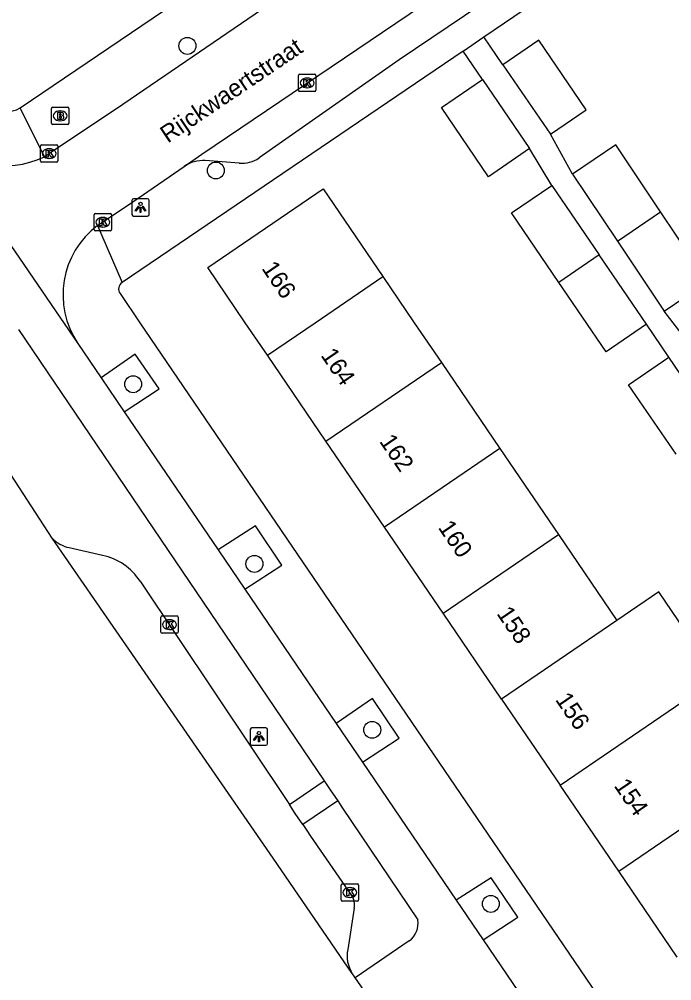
# Model space of a CAD drawing. Extents: x 160037 to 160839, y 385326 to 386441.
# Drawn here: x 160118.7 to 160156.4, y 385962.1 to 386017.5 of the extents above; entities that cross this region are included whole.
import ezdxf

# ---------------------------------------------------------------- set-up
doc = ezdxf.new("R2010")
doc.units = 0
for name, color, linetype in [('IMGEO_Boom', 7, 'Continuous'), ('IMGEO_Brandkraan', 7, 'Continuous'), ('IMGEO_Fietspad_gesloten', 7, 'Continuous'), ('IMGEO_Kolk', 7, 'Continuous'), ('IMGEO_Lichtpunt', 7, 'Continuous'), ('IMGEO_Openbare_ruimte_label', 7, 'Continuous'), ('IMGEO_Pand', 7, 'Continuous'), ('IMGEO_Pand_nummerreeks', 7, 'Continuous'), ('IMGEO_Parkeervlak_open', 7, 'Continuous'), ('IMGEO_Rijbaan_lokaal_gesloten', 7, 'Continuous'), ('IMGEO_Rijbaan_lokaal_open', 7, 'Continuous'), ('IMGEO_Voetpad_open', 7, 'Continuous')]:
    doc.layers.add(name, color=color, linetype=linetype)

msp = doc.modelspace()

# ---------------------------------------------------------------- linework, layer by layer
at = {"layer": 'IMGEO_Boom'}
for centre in [(160128.397, 386015.969), (160130.04, 386008.784), (160125.268, 385996.455), (160132.266, 385986.096), (160139.065, 385976.526), (160145.912, 385966.485)]:
    msp.add_circle(centre, 0.489, dxfattribs=at)
at = {"layer": 'IMGEO_Brandkraan'}
for p, q in [((160120.627, 386012.435), (160121.479, 386012.435)), ((160120.552, 386011.509), (160120.552, 386012.361)), ((160121.04, 386012.215), (160121.065, 386012.215)), ((160121.553, 386012.361), (160121.553, 386011.509)), ((160121.479, 386011.435), (160120.627, 386011.435)), ((160121.063, 386011.655), (160121.038, 386011.655))]:
    msp.add_line(p, q, dxfattribs=at)
for points in [[(160120.627, 386012.435), (160121.479, 386012.435)], [(160120.552, 386011.509), (160120.552, 386012.361)], [(160120.9, 386012.135), (160120.9, 386011.735), (160121.113, 386011.735)], [(160121.131, 386012.135), (160120.9, 386012.135)], [(160121.079, 386012.054), (160121.025, 386012.054), (160121.025, 386011.978)], [(160121.025, 386011.978), (160121.078, 386011.978)], [(160121.087, 386011.902), (160121.025, 386011.902), (160121.025, 386011.821)], [(160121.553, 386012.361), (160121.553, 386011.509)], [(160121.479, 386011.435), (160120.627, 386011.435)], [(160121.025, 386011.821), (160121.087, 386011.821)]]:
    msp.add_lwpolyline(points, dxfattribs=at)
for centre, radius, start, end in [((160120.629, 386012.359), 0.0765, 91.552, 178.448), ((160120.629, 386012.359), 0.0765, 91.552, 178.448), ((160121.477, 386012.359), 0.0765, 1.552, 88.448), ((160121.477, 386012.359), 0.0765, 1.552, 88.448), ((160121.08, 386012.016), 0.0379, 267.8285, 90.9355), ((160121.088, 386011.861), 0.0404, 269.8759, 90.5077), ((160121.135, 386011.99), 0.145, 59.4692, 91.5367), ((160121.16, 386012.037), 0.0922, 285.5137, 58.1501), ((160121.165, 386011.845), 0.105, 301.3115, 78.989), ((160120.629, 386011.511), 0.0765, 181.552, 268.448), ((160120.629, 386011.511), 0.0765, 181.552, 268.448), ((160121.119, 386011.986), 0.251, 268.6676, 293.5347), ((160121.477, 386011.511), 0.0765, 271.552, 358.448), ((160121.477, 386011.511), 0.0765, 271.552, 358.448)]:
    msp.add_arc(centre, radius, start, end, dxfattribs=at)
for centre, major_axis, ratio, start_param, end_param in [((160121.039, 386011.935), (-0.387, 0.002), 0.722429, 4.712389, 7.853982), ((160121.064, 386011.935), (-0.39, 0.002), 0.717154, 1.570796, 4.712389)]:
    msp.add_ellipse(centre, major_axis=major_axis, ratio=ratio, start_param=start_param, end_param=end_param, dxfattribs=at)
at = {"layer": 'IMGEO_Fietspad_gesloten'}
for points in [[(160118.645, 385999.609), (160136.295, 385973.586)], [(160122.081, 385998.808), (160123.429, 385996.826)], [(160123.429, 385996.826), (160124.758, 385994.871)], [(160124.758, 385994.871), (160130.172, 385986.909)], [(160130.172, 385986.909), (160131.713, 385984.643)], [(160131.713, 385984.643), (160136.979, 385976.896)], [(160136.979, 385976.896), (160138.5, 385974.658)], [(160138.5, 385974.658), (160143.914, 385966.694)], [(160136.295, 385973.586), (160136.648, 385973.065), (160137.081, 385972.428)], [(160137.081, 385972.428), (160137.322, 385972.072), (160141.694, 385965.572)], [(160143.914, 385966.694), (160145.465, 385964.411)], [(160141.197, 385964.348), (160138.083, 385962.227)], [(160145.465, 385964.411), (160150.233, 385957.4)]]:
    msp.add_lwpolyline(points, dxfattribs=at)
msp.add_arc((160140.463, 385965.359), 1.249, 305.9754, 9.8258, dxfattribs=at)
at = {"layer": 'IMGEO_Kolk'}
for p, q in [((160134.806, 386013.407), (160134.806, 386014.259)), ((160134.881, 386014.333), (160135.733, 386014.333)), ((160135.294, 386014.113), (160135.319, 386014.113)), ((160135.807, 386014.259), (160135.807, 386013.407)), ((160135.317, 386013.553), (160135.292, 386013.553)), ((160135.733, 386013.333), (160134.881, 386013.333)), ((160119.998, 386010.259), (160120.85, 386010.259)), ((160119.923, 386009.333), (160119.923, 386010.185)), ((160120.411, 386010.039), (160120.436, 386010.039)), ((160120.924, 386010.185), (160120.924, 386009.333)), ((160120.85, 386009.259), (160119.998, 386009.259)), ((160120.434, 386009.479), (160120.409, 386009.479)), ((160123.014, 386005.372), (160123.014, 386006.224)), ((160123.089, 386006.298), (160123.941, 386006.298)), ((160123.502, 386006.078), (160123.527, 386006.078)), ((160124.015, 386006.224), (160124.015, 386005.372)), ((160123.941, 386005.298), (160123.089, 386005.298)), ((160123.525, 386005.518), (160123.5, 386005.518)), ((160126.944, 385983.091), (160127.796, 385983.091)), ((160126.869, 385982.165), (160126.869, 385983.017)), ((160127.357, 385982.871), (160127.382, 385982.871)), ((160127.87, 385983.017), (160127.87, 385982.165)), ((160127.796, 385982.091), (160126.944, 385982.091)), ((160127.38, 385982.311), (160127.355, 385982.311)), ((160137.277, 385966.718), (160137.277, 385967.57)), ((160137.352, 385967.644), (160138.204, 385967.644)), ((160138.278, 385967.57), (160138.278, 385966.718)), ((160137.765, 385967.424), (160137.79, 385967.424)), ((160138.204, 385966.644), (160137.352, 385966.644)), ((160137.788, 385966.864), (160137.763, 385966.864))]:
    msp.add_line(p, q, dxfattribs=at)
for points in [[(160134.806, 386013.407), (160134.806, 386014.259)], [(160134.881, 386014.333), (160135.733, 386014.333)], [(160135.807, 386014.259), (160135.807, 386013.407)], [(160135.127, 386014.033), (160135.25, 386014.033), (160135.25, 386013.882), (160135.38, 386014.033), (160135.544, 386014.033), (160135.398, 386013.882), (160135.551, 386013.633), (160135.399, 386013.633), (160135.314, 386013.797), (160135.25, 386013.73), (160135.25, 386013.633), (160135.127, 386013.633), (160135.127, 386014.033)], [(160135.733, 386013.333), (160134.881, 386013.333)], [(160119.998, 386010.259), (160120.85, 386010.259)], [(160119.923, 386009.333), (160119.923, 386010.185)], [(160120.244, 386009.959), (160120.367, 386009.959), (160120.367, 386009.808), (160120.497, 386009.959), (160120.661, 386009.959), (160120.515, 386009.808), (160120.668, 386009.559), (160120.516, 386009.559), (160120.431, 386009.723), (160120.367, 386009.656), (160120.367, 386009.559), (160120.244, 386009.559), (160120.244, 386009.959)], [(160120.924, 386010.185), (160120.924, 386009.333)], [(160120.85, 386009.259), (160119.998, 386009.259)], [(160123.014, 386005.372), (160123.014, 386006.224)], [(160123.089, 386006.298), (160123.941, 386006.298)], [(160123.335, 386005.998), (160123.458, 386005.998), (160123.458, 386005.847), (160123.588, 386005.998), (160123.752, 386005.998), (160123.606, 386005.847), (160123.759, 386005.598), (160123.607, 386005.598), (160123.522, 386005.762), (160123.458, 386005.695), (160123.458, 386005.598), (160123.335, 386005.598), (160123.335, 386005.998)], [(160124.015, 386006.224), (160124.015, 386005.372)], [(160123.941, 386005.298), (160123.089, 386005.298)], [(160126.944, 385983.091), (160127.796, 385983.091)], [(160126.869, 385982.165), (160126.869, 385983.017)], [(160127.19, 385982.791), (160127.313, 385982.791), (160127.313, 385982.64), (160127.443, 385982.791), (160127.607, 385982.791), (160127.461, 385982.64), (160127.614, 385982.391), (160127.462, 385982.391), (160127.377, 385982.555), (160127.313, 385982.488), (160127.313, 385982.391), (160127.19, 385982.391), (160127.19, 385982.791)], [(160127.87, 385983.017), (160127.87, 385982.165)], [(160127.796, 385982.091), (160126.944, 385982.091)], [(160137.277, 385966.718), (160137.277, 385967.57)], [(160137.352, 385967.644), (160138.204, 385967.644)], [(160138.278, 385967.57), (160138.278, 385966.718)], [(160137.598, 385967.344), (160137.721, 385967.344), (160137.721, 385967.193), (160137.851, 385967.344), (160138.015, 385967.344), (160137.869, 385967.193), (160138.022, 385966.944), (160137.87, 385966.944), (160137.785, 385967.108), (160137.721, 385967.041), (160137.721, 385966.944), (160137.598, 385966.944), (160137.598, 385967.344)], [(160138.204, 385966.644), (160137.352, 385966.644)]]:
    msp.add_lwpolyline(points, dxfattribs=at)
for centre, start, end in [((160134.883, 386014.257), 91.552, 178.448), ((160134.883, 386014.257), 91.552, 178.448), ((160135.731, 386014.257), 1.552, 88.448), ((160135.731, 386014.257), 1.552, 88.448), ((160134.883, 386013.409), 181.552, 268.448), ((160134.883, 386013.409), 181.552, 268.448), ((160135.731, 386013.409), 271.552, 358.448), ((160135.731, 386013.409), 271.552, 358.448), ((160120, 386010.183), 91.552, 178.448), ((160120, 386010.183), 91.552, 178.448), ((160120.848, 386010.183), 1.552, 88.448), ((160120.848, 386010.183), 1.552, 88.448), ((160120, 386009.335), 181.552, 268.448), ((160120, 386009.335), 181.552, 268.448), ((160120.848, 386009.335), 271.552, 358.448), ((160120.848, 386009.335), 271.552, 358.448), ((160123.091, 386006.222), 91.552, 178.448), ((160123.091, 386006.222), 91.552, 178.448), ((160123.939, 386006.222), 1.552, 88.448), ((160123.939, 386006.222), 1.552, 88.448), ((160123.091, 386005.374), 181.552, 268.448), ((160123.091, 386005.374), 181.552, 268.448), ((160123.939, 386005.374), 271.552, 358.448), ((160123.939, 386005.374), 271.552, 358.448), ((160126.946, 385983.015), 91.552, 178.448), ((160126.946, 385983.015), 91.552, 178.448), ((160127.794, 385983.015), 1.552, 88.448), ((160127.794, 385983.015), 1.552, 88.448), ((160126.946, 385982.167), 181.552, 268.448), ((160126.946, 385982.167), 181.552, 268.448), ((160127.794, 385982.167), 271.552, 358.448), ((160127.794, 385982.167), 271.552, 358.448), ((160137.354, 385967.568), 91.552, 178.448), ((160137.354, 385967.568), 91.552, 178.448), ((160138.202, 385967.568), 1.552, 88.448), ((160138.202, 385967.568), 1.552, 88.448), ((160137.354, 385966.72), 181.552, 268.448), ((160137.354, 385966.72), 181.552, 268.448), ((160138.202, 385966.72), 271.552, 358.448), ((160138.202, 385966.72), 271.552, 358.448)]:
    msp.add_arc(centre, 0.0765, start, end, dxfattribs=at)
for centre, major_axis, ratio, start_param, end_param in [((160135.293, 386013.833), (-0.387, 0.002), 0.722429, 4.712389, 7.853982), ((160135.318, 386013.833), (-0.39, 0.002), 0.717154, 1.570796, 4.712389), ((160120.41, 386009.759), (-0.387, 0.002), 0.722429, 4.712389, 7.853982), ((160120.435, 386009.759), (-0.39, 0.002), 0.717154, 1.570796, 4.712389), ((160123.501, 386005.798), (-0.387, 0.002), 0.722429, 4.712389, 7.853982), ((160123.526, 386005.798), (-0.39, 0.002), 0.717154, 1.570796, 4.712389), ((160127.356, 385982.591), (-0.387, 0.002), 0.722429, 4.712389, 7.853982), ((160127.381, 385982.591), (-0.39, 0.002), 0.717154, 1.570796, 4.712389), ((160137.764, 385967.144), (-0.387, 0.002), 0.722429, 4.712389, 7.853982), ((160137.789, 385967.144), (-0.39, 0.002), 0.717154, 1.570796, 4.712389)]:
    msp.add_ellipse(centre, major_axis=major_axis, ratio=ratio, start_param=start_param, end_param=end_param, dxfattribs=at)
at = {"layer": 'IMGEO_Lichtpunt'}
for p, q in [((160125.197, 386007.059), (160125.197, 386006.252)), ((160125.197, 386007.059), (160125.197, 386006.252)), ((160126.099, 386007.154), (160125.291, 386007.154)), ((160126.099, 386007.154), (160125.291, 386007.154)), ((160126.193, 386006.252), (160126.193, 386007.059)), ((160126.193, 386006.252), (160126.193, 386007.059)), ((160125.291, 386006.158), (160126.099, 386006.158)), ((160125.291, 386006.158), (160126.099, 386006.158)), ((160132.028, 385976.54), (160132.028, 385975.733)), ((160132.028, 385976.54), (160132.028, 385975.733)), ((160132.93, 385976.635), (160132.122, 385976.635)), ((160132.93, 385976.635), (160132.122, 385976.635)), ((160133.024, 385975.733), (160133.024, 385976.54)), ((160133.024, 385975.733), (160133.024, 385976.54)), ((160132.122, 385975.639), (160132.93, 385975.639)), ((160132.122, 385975.639), (160132.93, 385975.639))]:
    msp.add_line(p, q, dxfattribs=at)
for points in [[(160125.571, 386006.723), (160125.61, 386006.695), (160125.422, 386006.433), (160125.384, 386006.46), (160125.571, 386006.723)], [(160125.673, 386006.675), (160125.72, 386006.675), (160125.72, 386006.353), (160125.673, 386006.353), (160125.673, 386006.675)], [(160125.783, 386006.695), (160125.821, 386006.722), (160126.008, 386006.46), (160125.969, 386006.432), (160125.783, 386006.695)], [(160132.402, 385976.204), (160132.441, 385976.176), (160132.253, 385975.914), (160132.215, 385975.941), (160132.402, 385976.204)], [(160132.504, 385976.156), (160132.551, 385976.156), (160132.551, 385975.834), (160132.504, 385975.834), (160132.504, 385976.156)], [(160132.614, 385976.176), (160132.652, 385976.203), (160132.839, 385975.941), (160132.8, 385975.913), (160132.614, 385976.176)]]:
    msp.add_lwpolyline(points, dxfattribs=at)
for centre in [(160125.696, 386006.857), (160132.527, 385976.338)]:
    msp.add_circle(centre, 0.0994, dxfattribs=at)
for centre, start, end in [((160125.291, 386007.059), 90, 180), ((160125.291, 386007.059), 90, 180), ((160126.099, 386007.059), 0, 90), ((160126.099, 386007.059), 0, 90), ((160125.291, 386006.252), 180, 270), ((160125.291, 386006.252), 180, 270), ((160126.099, 386006.252), 270, 0), ((160126.099, 386006.252), 270, 360), ((160132.122, 385976.54), 90, 180), ((160132.122, 385976.54), 90, 180), ((160132.93, 385976.54), 0, 90), ((160132.93, 385976.54), 0, 90), ((160132.122, 385975.733), 180, 270), ((160132.122, 385975.733), 180, 270), ((160132.93, 385975.733), 270, 0), ((160132.93, 385975.733), 270, 360)]:
    msp.add_arc(centre, 0.0946, start, end, dxfattribs=at)
at = {"layer": 'IMGEO_Pand'}
for points in [[(160149.354, 386010.869), (160151.42, 386012.283), (160148.674, 386016.298), (160146.608, 386014.884)], [(160146.608, 386014.884), (160149.354, 386010.869)], [(160148.149, 386010.046), (160145.782, 386008.427), (160143.058, 386012.409), (160145.425, 386014.028)], [(160145.425, 386014.028), (160148.149, 386010.046)], [(160155.713, 386006.402), (160153.125, 386010.255), (160150.622, 386008.574)], [(160150.622, 386008.574), (160153.214, 386004.713)], [(160133.017, 385998.126), (160131.74, 386000), (160129.572, 386003.181), (160136.231, 386007.72), (160139.676, 386002.666)], [(160149.841, 386002.33), (160147.108, 386006.339), (160149.435, 386007.925)], [(160149.435, 386007.925), (160152.168, 386003.916)], [(160153.214, 386004.713), (160155.713, 386006.402)], [(160155.924, 386000.678), (160158.424, 386002.367), (160155.713, 386006.402)], [(160153.214, 386004.713), (160155.924, 386000.678)], [(160152.168, 386003.916), (160149.841, 386002.33)], [(160154.895, 385999.915), (160152.168, 386003.916)], [(160133.017, 385998.126), (160135.766, 386000), (160139.676, 386002.666)], [(160139.676, 386002.666), (160141.493, 386000), (160143.056, 385997.707)], [(160154.895, 385999.915), (160152.569, 385998.33), (160149.841, 386002.33)], [(160136.397, 385993.168), (160133.017, 385998.126)], [(160156.6, 385992.416), (160153.867, 385996.425), (160156.193, 385998.01)], [(160158.926, 385994.001), (160156.193, 385998.01)], [(160136.397, 385993.168), (160143.056, 385997.707)], [(160143.056, 385997.707), (160146.435, 385992.75)], [(160139.776, 385988.21), (160136.397, 385993.168)], [(160146.435, 385992.75), (160139.776, 385988.21)], [(160146.435, 385992.75), (160149.814, 385987.792)], [(160143.155, 385983.253), (160139.776, 385988.21)], [(160143.155, 385983.253), (160149.814, 385987.792)], [(160149.814, 385987.792), (160153.194, 385982.834)], [(160156.574, 385977.876), (160158.983, 385979.518), (160155.603, 385984.476), (160153.194, 385982.834)], [(160146.535, 385978.295), (160143.155, 385983.253)], [(160153.194, 385982.834), (160146.535, 385978.295)], [(160146.535, 385978.295), (160149.914, 385973.337)], [(160149.914, 385973.337), (160156.574, 385977.876)], [(160153.293, 385968.379), (160149.914, 385973.337)], [(160153.293, 385968.379), (160159.953, 385972.919)], [(160156.673, 385963.421), (160153.293, 385968.379)]]:
    msp.add_lwpolyline(points, dxfattribs=at)
at = {"layer": 'IMGEO_Parkeervlak_open'}
for points in [[(160121.565, 385987.033), (160123.497, 385986.589)], [(160125.664, 385985.097), (160134.284, 385972.222)], [(160135.063, 385971.058), (160135.296, 385970.711), (160135.512, 385970.389), (160137.871, 385966.98)], [(160138.024, 385966.238), (160137.652, 385963.859)]]:
    msp.add_lwpolyline(points, dxfattribs=at)
for centre, radius, start, end in [((160121.984, 385988.922), 1.935, 224.1159, 257.4944), ((160122.793, 385983.247), 3.415, 32.7974, 78.107), ((160137.035, 385966.421), 1.006, 349.5336, 33.7686), ((160139.487, 385963.489), 1.872, 168.6094, 212.8794)]:
    msp.add_arc(centre, radius, start, end, dxfattribs=at)
at = {"layer": 'IMGEO_Rijbaan_lokaal_gesloten'}
for points in [[(160120.595, 385987.575), (160116.757, 385993.446)], [(160137.915, 385962.473), (160133.356, 385969.12), (160120.595, 385987.575)], [(160138.083, 385962.227), (160137.984, 385962.372), (160137.915, 385962.473)], [(160139.703, 385959.857), (160139.542, 385960.093), (160138.154, 385962.123), (160138.083, 385962.227)]]:
    msp.add_lwpolyline(points, dxfattribs=at)
at = {"layer": 'IMGEO_Rijbaan_lokaal_open'}
for points in [[(160159.266, 386036.142), (160139.533, 386022.738), (160124.669, 386012.596), (160120.145, 386009.569)], [(160128.204, 386009.022), (160129.232, 386009.733), (160151.628, 386024.852), (160157.666, 386028.94)], [(160113.781, 386010.901), (160122.081, 385998.808)], [(160123.219, 386005.61), (160125.251, 386006.979), (160128.204, 386009.022)]]:
    msp.add_lwpolyline(points, dxfattribs=at)
for centre, radius, start, end in [((160117.848, 386014.466), 5.408, 221.2297, 295.1273), ((160126.212, 386001.613), 4.993, 126.824, 214.1803)]:
    msp.add_arc(centre, radius, start, end, dxfattribs=at)
at = {"layer": 'IMGEO_Voetpad_open'}
for points in [[(160118.738, 386012.393), (160166.76, 386044.877)], [(160145.517, 386016.492), (160163.057, 386028.392)], [(160155.79, 386025.406), (160151.881, 386022.76), (160140.615, 386015.168), (160132.539, 386009.506)], [(160144.309, 386015.673), (160145.517, 386016.492)], [(160146.608, 386014.884), (160145.517, 386016.492)], [(160144.309, 386015.673), (160124.631, 386002.322)], [(160145.425, 386014.028), (160144.309, 386015.673)], [(160120.145, 386009.569), (160118.738, 386012.393)], [(160150.622, 386008.574), (160149.354, 386010.869)], [(160149.435, 386007.925), (160148.149, 386010.046)], [(160131.393, 386009.203), (160129.432, 386009.354)], [(160123.219, 386005.61), (160124.631, 386002.322)], [(160124.511, 386001.685), (160125.658, 386000), (160176.803, 385924.884)], [(160157.409, 385998.723), (160155.924, 386000.678)], [(160156.193, 385998.01), (160154.895, 385999.915)], [(160124.758, 385994.871), (160126.769, 385996.183), (160125.389, 385998.197), (160123.429, 385996.826)], [(160131.713, 385984.643), (160133.846, 385986.031), (160132.331, 385988.289), (160130.172, 385986.909)], [(160138.5, 385974.658), (160140.621, 385976.036), (160139.091, 385978.325), (160136.979, 385976.896)], [(160134.284, 385972.222), (160136.295, 385973.586)], [(160135.063, 385971.058), (160134.628, 385971.708), (160134.284, 385972.222)], [(160137.081, 385972.428), (160135.063, 385971.058)], [(160145.465, 385964.411), (160147.48, 385965.729), (160145.937, 385967.983), (160143.914, 385966.694)]]:
    msp.add_lwpolyline(points, dxfattribs=at)
for centre, radius, start, end in [((160118.082, 386013.369), 1.176, 214.3749, 303.9141), ((160129.343, 386007.248), 2.108, 87.5696, 122.6878), ((160131.534, 386010.989), 1.791, 265.4858, 304.1342), ((160124.889, 386001.944), 0.458, 124.3295, 214.3335)]:
    msp.add_arc(centre, radius, start, end, dxfattribs=at)

# ---------------------------------------------------------------- texts
at = {"layer": 'IMGEO_Openbare_ruimte_label'}
msp.add_text('Rijckwaertstraat', height=1, rotation=34.0395, dxfattribs=at).set_placement((160127.264, 386010.334))
at = {"layer": 'IMGEO_Pand_nummerreeks'}
for s, rotation, p in [('166', 304.2788, (160132.652, 386003.136)), ('164', 304.2816, (160136.063, 385998.124)), ('162', 304.2816, (160139.447, 385993.161)), ('160', 304.2816, (160142.834, 385988.192)), ('158', 304.2816, (160146.218, 385983.227)), ('156', 304.2799, (160149.601, 385978.265)), ('154', 304.2816, (160152.985, 385973.301))]:
    msp.add_text(s, height=1, rotation=rotation, dxfattribs=at).set_placement(p)

doc.saveas('drawing.dxf')
